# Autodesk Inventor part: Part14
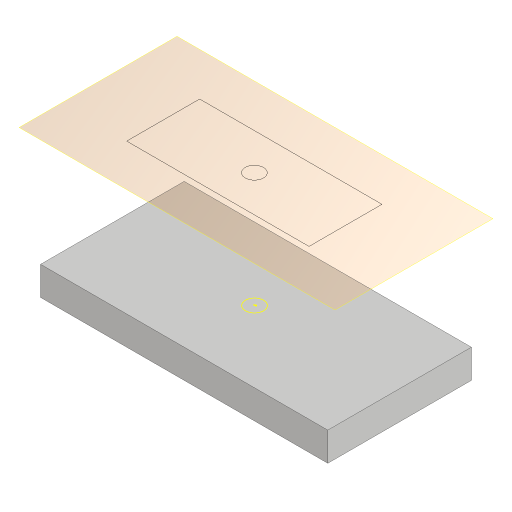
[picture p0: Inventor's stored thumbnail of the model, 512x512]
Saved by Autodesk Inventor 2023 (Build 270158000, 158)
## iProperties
Created: 2015-05
Part Number: Part14
Material: Generic
Document SubType Name: Modeling
Designer: Sandeep
Density: 1 g/cm^3
Appearance: Default
Author: Sandeep
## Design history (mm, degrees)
sketch "Sketch1"
  geometry: L1 (-100, 50)-(100, 50); L2 (100, 50)-(100, -50); L3 (100, -50)-(-100, -50); L4 (-100, -50)-(-100, 50); 1 further point
  constraints: 8 end point, 2 parallel, 1 horizontal, 1 perpendicular
  dimensions: "d0" = 100 distance from line of point (0, 0) L2; "d1" = 200 distance of L1.start L1.end; "d2" = 50 distance from line of point (0, 0) L1; "d3" = 100 distance of L1.end L2.end
extrude "Extrusion1" new body sketch "Sketch1" distance "d4" = 20; taper "d5" = 0 deg
workplane "Work Plane1"
sketch "Sketch2"
  geometry: C1 r 6.35 at (-0.807, -0.346) reference; 1 further point
body "Solid1"
